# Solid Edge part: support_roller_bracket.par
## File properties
Title: Support roller bracket
Author: Abhinav Rai
Template: Normal.par
Last saved by: TIET
Revision: 19
Application: Solid Edge
Density: 0 kg/mm^3
Accuracy: 0.99
Material: aluminum
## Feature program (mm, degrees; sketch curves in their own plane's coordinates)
sketch for "unnamed Protrusion 1" #1 plane through (0, 0, 0) normal (0, -1, 0) x-axis (1, 0, 0)
  circle centre (0, -138.9237) radius 3.81
sketch for "unnamed Protrusion 1" #2 plane through (0, 0, 0) normal (0, -1, 0) x-axis (1, 0, 0)
  line (143.637, -99.9249) -> (-143.637, -99.9249)
  line (-143.637, -99.9249) -> (-143.637, -115.1647)
  line (-143.637, -115.1647) -> (-61.0846, -156.7704)
  line (-61.0846, -156.7704) -> (-61.0846, -162.9363)
  line (-61.0846, -162.9363) -> (61.0846, -162.9363)
  line (61.0846, -156.7704) -> (61.0846, -162.9363)
  line (143.637, -115.1647) -> (61.0846, -156.7704)
  line (143.637, -99.9249) -> (143.637, -115.1647)
  dimension (linear) = 143.637
extrude "unnamed Protrusion 1" add finite 101.6 symmetric
fillet "Round_1" radius 31.75
fillet "Round_2" radius 6.35
sketch for "unnamed Protrusion 2" plane through (0, 0, 67.2512) normal (1, 0, 0) x-axis (0, 1, 0)
  arc centre (-23.4135, -61.792) radius 19.05 from (-23.4135, -42.742) to (-42.405, -60.3002) ccw
  line (-50.8, -167.1761) -> (-42.405, -60.3002)
  line (-50.8, -167.1761) -> (50.8, -167.1761)
  line (45.7777, -60.8928) -> (50.8, -167.1761)
  arc centre (26.749, -61.792) radius 19.05 from (26.749, -42.742) to (45.7777, -60.8928) cw
  line (19.05, -42.742) -> (26.749, -42.742)
  line (19.05, -64.967) -> (19.05, -42.742)
  arc centre (0, -64.967) radius 19.05 from (-19.05, -64.967) to (19.05, -64.967) ccw
  line (-19.05, -42.742) -> (-19.05, -64.967)
  line (-23.4135, -42.742) -> (-19.05, -42.742)
extrude "unnamed Protrusion 2" add to key point symmetric
sketch for "ExtrudedCutout_1" plane through (0, 0, 0) normal (0, -1, 0) x-axis (1, 0, 0)
  line (-128.3193, 24.5092) -> (125.6319, 24.5092)
  line (125.6319, 24.5092) -> (125.6319, -99.9249)
  line (125.6319, -99.9249) -> (-128.3193, -99.9249)
  line (-128.3193, -99.9249) -> (-128.3193, 24.5092)
extrude "ExtrudedCutout_1" cut finite 203.2 symmetric
chamfer "Chamfer_1" setback 5.08
rib "Rib_1"  Thickness = 25.4 mm
mirror "unnamed Mirror 1" of "Rib_1" about plane through (0, 0, 0) normal (1, 0, 0)
rib "unnamed Rib 1"
sketch for "Hole_1" plane through (0.1259, 0, -162.9363) normal (0, 0, -1) x-axis (-1, 0, 0)
  hole centre (0.1259, 0) bore radius 25.4
hole "Hole_1" diameter 50.8 through
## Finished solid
Body 1: solid body, 55 faces, 142 edges, 86 vertices.
  Faces by surface: plane 38, cylinder 17
  Edges by curve: line 106, circle 34, intersection 2
Bounding box of the edges (mm): 379.121 x 101.600 x 187.446, from (-189.5605, -50.8, -162.9363) to (189.5605, 50.8, 24.5092).
Cylindrical faces by radius (mm): R3.81 x2, R6.35 x2, R19.05 x6, R25.4 x1, R31.75 x4, R55.372 x2
Planar faces by outward normal: +x 4, +y 5, +z 5, -x 4, -y 5, -z 1, oblique 14
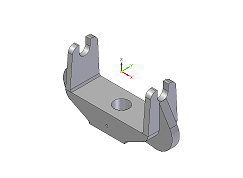
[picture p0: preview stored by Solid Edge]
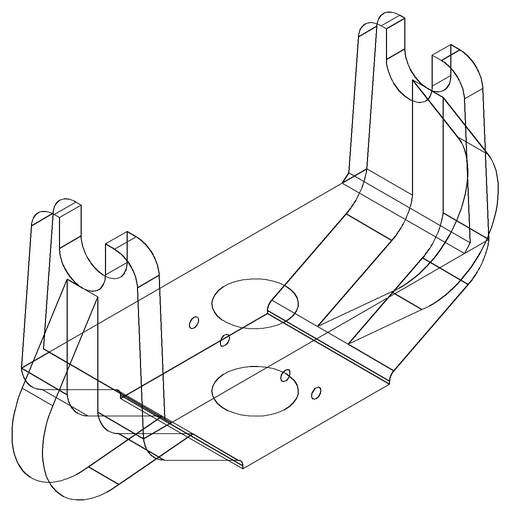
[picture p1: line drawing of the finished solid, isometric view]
